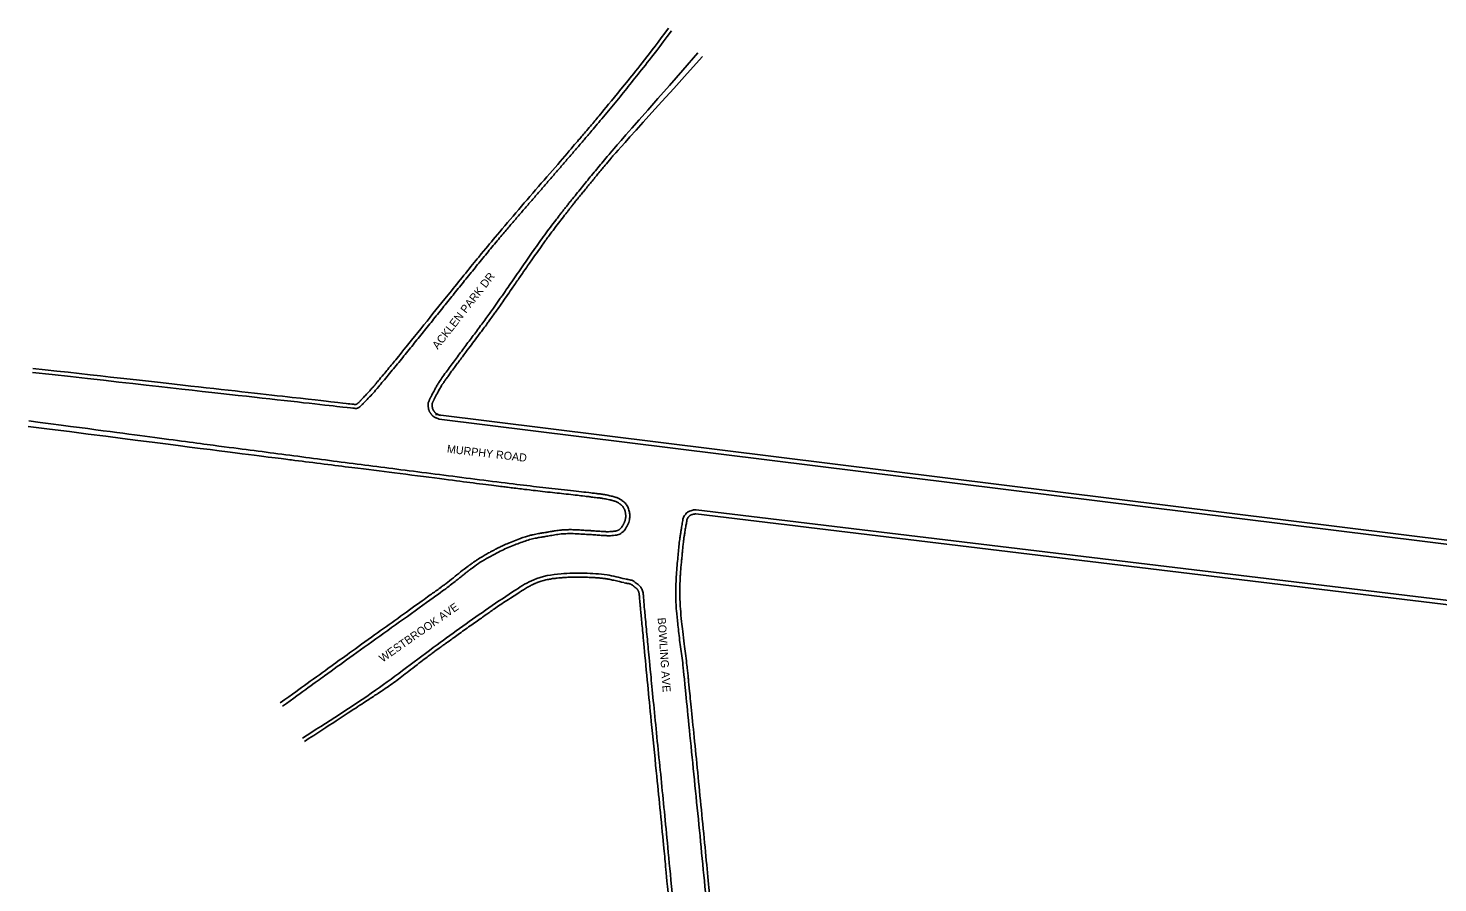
# Model space of a CAD drawing. Extents: x 1723992 to 1732080, y 650782 to 665122.
# Drawn here: x 1723992 to 1725049, y 658436 to 659077 of the extents above; entities that cross this region are included whole.
import ezdxf

# ---------------------------------------------------------------- set-up
doc = ezdxf.new("R2010")
doc.units = 0
for name, color, linetype in [('SURVEY - TRANSPORTATION - Features', 7, 'Continuous'), ('SURVEY - TRANSPORTATION - Roads', 7, 'Continuous'), ('SURVEY - TRANSPORTATION - Roads Text', 7, 'Continuous')]:
    doc.layers.add(name, color=color, linetype=linetype)

msp = doc.modelspace()

# ---------------------------------------------------------------- linework, layer by layer
at = {"layer": 'SURVEY - TRANSPORTATION - Features'}
for points in [[(1724297.3, 658787.4), (1725146.1, 658682), (1725172, 658680.1), (1725213.9, 658676.9), (1725217.3, 658676.6)], [(1724492.5, 658712.9), (1725143.7, 658634.3)]]:
    msp.add_lwpolyline(points, dxfattribs=at)
for points in [[(1724472, 659077.2), (1724456.9, 659056.9), (1724441.2, 659037.1), (1724420.9, 659012.6), (1724416.8, 659007.6), (1724408.4, 658997.7), (1724404.2, 658992.8), (1724391.6, 658978), (1724374.5, 658958.4), (1724357.6, 658938.8), (1724340.8, 658918.9), (1724332.5, 658908.9), (1724307.9, 658878.7), (1724291.7, 658858.4), (1724271.3, 658833.2), (1724265.2, 658825.7), (1724258, 658816.9), (1724254.3, 658812.6), (1724252.6, 658810.5), (1724252, 658809.8), (1724251.7, 658809.4), (1724251.6, 658809.3), (1724251.2, 658808.8), (1724251, 658808.5), (1724248.6, 658805.9), (1724246.5, 658803.5), (1724243.7, 658800.6), (1724242.8, 658799.7), (1724241.9, 658798.7), (1724241.4, 658798.2), (1724241.2, 658798), (1724241.2, 658797.9), (1724241, 658797.8), (1724240.9, 658797.7), (1724240.3, 658797), (1724239.8, 658796.5), (1724239.2, 658795.9), (1724238.9, 658795.7), (1724238.6, 658795.5), (1724238.5, 658795.4), (1724238.3, 658795.3), (1724238.3, 658795.3), (1724238.3, 658795.3), (1724238.3, 658795.3), (1724238.3, 658795.3), (1724238.2, 658795.2), (1724238.2, 658795.2), (1724238, 658795.1), (1724237.9, 658795.1), (1724237.6, 658795.1), (1724237.3, 658795), (1724237, 658795.1), (1724237, 658795.1), (1724236.9, 658795.1), (1724236.9, 658795.1), (1724236.8, 658795.1), (1724236.8, 658795.1), (1724236.7, 658795.1), (1724236.5, 658795.1), (1724235.8, 658795.2), (1724233.6, 658795.4), (1724228.4, 658796), (1724197.7, 658799.5), (1724119.6, 658808.2), (1724044.7, 658816.6), (1723995.6, 658822.1)], [(1724497.5, 659055.9), (1724432.4, 658983.8), (1724429.1, 658979.8), (1724424, 658973.7), (1724422.3, 658971.7), (1724418.9, 658967.6), (1724417.2, 658965.5), (1724413.8, 658961.4), (1724412.1, 658959.3), (1724408.8, 658955.2), (1724407.1, 658953.1), (1724403.7, 658949), (1724402.1, 658946.9), (1724399.6, 658943.8), (1724398.7, 658942.7), (1724397.1, 658940.6), (1724396.3, 658939.6), (1724392.1, 658934.3), (1724388.9, 658930.1), (1724384.1, 658923.7), (1724382.5, 658921.6), (1724379.4, 658917.3), (1724377.9, 658915.1), (1724373.2, 658908.6), (1724370.1, 658904.3), (1724364, 658895.5), (1724361, 658891.1), (1724354.9, 658882.3), (1724351.9, 658877.9), (1724347.3, 658871.3), (1724345.8, 658869.1), (1724342.7, 658864.7), (1724341.1, 658862.6), (1724337.9, 658858.2), (1724336.4, 658856), (1724333.2, 658851.7), (1724331.6, 658849.6), (1724326.8, 658843.1), (1724323.6, 658838.9), (1724318.8, 658832.4), (1724317.2, 658830.3), (1724314, 658826), (1724312.4, 658823.9), (1724309.2, 658819.6), (1724307.7, 658817.4), (1724305.4, 658814.2), (1724304.4, 658812.8), (1724303.5, 658811.5), (1724303.1, 658810.9), (1724302.9, 658810.7), (1724302.4, 658809.9), (1724302.1, 658809.4), (1724301.1, 658807.8), (1724300.4, 658806.6), (1724299.5, 658804.9), (1724299.2, 658804.3), (1724298.5, 658803.1), (1724297.9, 658802), (1724297.3, 658800.8), (1724296.9, 658800.1), (1724296.8, 658800), (1724296.7, 658799.7), (1724296.6, 658799.6), (1724296.4, 658799.1), (1724296.3, 658798.8), (1724296.1, 658798.4), (1724296, 658798.2), (1724295.9, 658798), (1724295.9, 658797.9), (1724295.8, 658797.8), (1724295.6, 658797.4), (1724295.5, 658797.1), (1724295.2, 658796.5), (1724295.1, 658796.3), (1724295, 658796), (1724295, 658795.9), (1724295, 658795.9), (1724295, 658795.9), (1724294.9, 658795.9), (1724294.9, 658795.8), (1724294.9, 658795.8), (1724294.9, 658795.7), (1724294.9, 658795.6), (1724294.8, 658795.4), (1724294.8, 658795.2), (1724294.8, 658794.8), (1724294.8, 658794.6), (1724294.8, 658794.3), (1724294.8, 658794.2), (1724294.8, 658794.1), (1724294.8, 658794.1), (1724294.8, 658794), (1724294.8, 658793.8), (1724294.9, 658793.6), (1724294.9, 658793.2), (1724295, 658793), (1724295.1, 658792.5), (1724295.1, 658792.2), (1724295.2, 658791.9), (1724295.2, 658791.8), (1724295.3, 658791.8), (1724295.3, 658791.7), (1724295.3, 658791.7), (1724295.3, 658791.7), (1724295.3, 658791.6), (1724295.4, 658791.5), (1724295.5, 658791.2), (1724295.6, 658791), (1724295.7, 658790.7), (1724295.8, 658790.6), (1724295.9, 658790.4), (1724296, 658790.3), (1724296.2, 658790.1), (1724296.2, 658790), (1724296.4, 658789.8), (1724296.5, 658789.6), (1724296.8, 658789.3), (1724296.9, 658789.1), (1724297.1, 658788.9), (1724297.1, 658788.9), (1724297.2, 658788.8), (1724297.2, 658788.8), (1724297.2, 658788.8), (1724297.2, 658788.8), (1724297.4, 658788.7), (1724297.5, 658788.6), (1724297.7, 658788.4), (1724297.9, 658788.2), (1724298.2, 658788), (1724298.4, 658788), (1724298.5, 658787.9), (1724298.5, 658787.9), (1724298.6, 658787.9), (1724298.6, 658787.9), (1724298.6, 658787.8), (1724298.7, 658787.8), (1724299, 658787.7), (1724299.8, 658787.4), (1724300.6, 658787), (1724301.2, 658786.8)], [(1723992, 658778.6), (1724166.8, 658756.2), (1724189.6, 658753.4), (1724238.4, 658747.3), (1724264.5, 658744), (1724303.6, 658739), (1724323.2, 658736.5), (1724342.8, 658734), (1724352.5, 658732.8), (1724355.8, 658732.4), (1724362.4, 658731.6), (1724365.6, 658731.2), (1724382, 658729.3), (1724395.1, 658727.9), (1724409.7, 658726.2), (1724411.4, 658726), (1724414.6, 658725.6), (1724416.2, 658725.4), (1724418.7, 658725.1), (1724419.9, 658725), (1724421.2, 658724.8), (1724421.7, 658724.7), (1724421.9, 658724.7), (1724422, 658724.7), (1724422.3, 658724.6), (1724424, 658724.4), (1724425.7, 658724), (1724428, 658723.5), (1724428.8, 658723.3), (1724430, 658723), (1724430.6, 658722.8), (1724431.2, 658722.7), (1724431.4, 658722.6), (1724431.5, 658722.6), (1724431.6, 658722.6), (1724431.7, 658722.5), (1724431.7, 658722.5), (1724432.4, 658722.3), (1724433, 658722), (1724434.2, 658721.4), (1724434.8, 658721), (1724435.5, 658720.5), (1724435.7, 658720.4), (1724435.9, 658720.2), (1724436, 658720.1), (1724436.1, 658720), (1724436.2, 658720), (1724436.5, 658719.7), (1724436.8, 658719.5), (1724437.4, 658718.9), (1724437.8, 658718.5), (1724438.3, 658717.7), (1724438.5, 658717.4), (1724438.8, 658716.8), (1724438.9, 658716.6), (1724439.3, 658715.7), (1724439.5, 658715.1), (1724439.7, 658714.1), (1724439.7, 658713.7), (1724439.8, 658713), (1724439.9, 658712.7), (1724440, 658711.6), (1724440, 658711), (1724439.9, 658710), (1724439.9, 658709.7), (1724439.8, 658709.1), (1724439.7, 658708.8), (1724439.5, 658707.9), (1724439.2, 658707.2), (1724438.8, 658706.3), (1724438.7, 658705.9), (1724438.4, 658705.4), (1724438.3, 658705.2), (1724438.1, 658704.9), (1724438, 658704.7), (1724437.6, 658703.9), (1724437.2, 658703.3), (1724436.5, 658702.4), (1724436.1, 658702), (1724435.4, 658701.4), (1724435.2, 658701.2), (1724434.7, 658700.9), (1724434.4, 658700.7), (1724433.6, 658700.4), (1724433.1, 658700.2), (1724432.3, 658700.1), (1724432.2, 658700), (1724432, 658700), (1724431.9, 658700), (1724431.8, 658700), (1724431.8, 658700), (1724431.8, 658700), (1724431.7, 658700), (1724431.6, 658700), (1724431.2, 658699.9), (1724430.7, 658699.9), (1724428.7, 658699.7), (1724427.2, 658699.6), (1724425.6, 658699.6), (1724425.3, 658699.6), (1724425, 658699.6), (1724424.9, 658699.7), (1724424.8, 658699.7), (1724424.7, 658699.7), (1724424.3, 658699.7), (1724423, 658699.8), (1724421.8, 658699.8), (1724419.3, 658700), (1724417.7, 658700.1), (1724415.2, 658700.3), (1724414.2, 658700.4), (1724413.1, 658700.4), (1724412.7, 658700.5), (1724412.5, 658700.5), (1724411.9, 658700.5), (1724411.5, 658700.5), (1724409.5, 658700.6), (1724407.8, 658700.8), (1724402.8, 658701), (1724399.5, 658701.2), (1724395.7, 658701.1), (1724395.2, 658701.1), (1724394.6, 658701.1), (1724394.4, 658701.1), (1724393.9, 658701.1), (1724392.8, 658701), (1724391.7, 658700.9), (1724389.2, 658700.6), (1724387.5, 658700.4), (1724384.2, 658699.8), (1724382.6, 658699.5), (1724379.3, 658699), (1724377.7, 658698.7), (1724374.4, 658698.1), (1724372.8, 658697.8), (1724370.3, 658697.3), (1724369.4, 658697.1), (1724367.8, 658696.7), (1724366.9, 658696.4), (1724362.8, 658695.2), (1724359.7, 658694), (1724353.5, 658691.6), (1724350.4, 658690.3), (1724345.8, 658688.2), (1724344.3, 658687.5), (1724342.4, 658686.5), (1724342, 658686.3), (1724341.3, 658685.9), (1724340.2, 658685.3), (1724339.1, 658684.7), (1724335.4, 658682.7), (1724332.5, 658681), (1724328.2, 658678.3), (1724326.8, 658677.4), (1724324.8, 658675.9), (1724324.1, 658675.4), (1724323, 658674.7), (1724322.7, 658674.4), (1724322, 658673.9), (1724321.7, 658673.7), (1724316, 658669.4), (1724311, 658665.2), (1724304.6, 658660.2), (1724303.3, 658659.3), (1724301.6, 658658.1), (1724301.3, 658657.8), (1724300.7, 658657.4), (1724299.7, 658656.6), (1724296, 658654), (1724287.3, 658647.8), (1724268.6, 658634.3), (1724252.6, 658622.8), (1724231.2, 658607.5), (1724220.6, 658599.8), (1724200.3, 658585.1), (1724190.6, 658578.2), (1724181, 658571.2)], [(1724525.8, 658181.9), (1724521.7, 658225.8), (1724515.5, 658292.4), (1724509.3, 658359), (1724506.1, 658393.1), (1724505.1, 658404.5), (1724502.9, 658427.2), (1724497.4, 658484), (1724491.8, 658540.7), (1724487.1, 658587.5), (1724487, 658588.9), (1724486.7, 658591.8), (1724486.2, 658596.1), (1724485.7, 658600.3), (1724484.7, 658608.9), (1724484, 658614.5), (1724482.6, 658625.8), (1724481.9, 658631.4), (1724480.9, 658642.7), (1724480.6, 658648.3), (1724480.5, 658656.7), (1724480.6, 658659.5), (1724480.8, 658665.1), (1724481, 658667.9), (1724481.3, 658672.2), (1724481.5, 658674.3), (1724481.7, 658676.4), (1724481.9, 658677.8), (1724481.9, 658678.5), (1724482.3, 658682.1), (1724482.5, 658684.9), (1724482.9, 658689.2), (1724483.1, 658690.5), (1724483.3, 658692.6), (1724483.4, 658693.5), (1724483.6, 658694.3), (1724483.6, 658694.7), (1724483.6, 658694.9), (1724483.7, 658695.4), (1724484.2, 658698.5), (1724484.8, 658702.4), (1724485.5, 658706.2), (1724485.7, 658707.5), (1724485.8, 658708.1), (1724485.8, 658708.3), (1724485.8, 658708.5), (1724485.8, 658708.5), (1724485.8, 658708.5), (1724485.8, 658708.5), (1724485.8, 658708.5), (1724485.9, 658708.9), (1724486.1, 658709.2), (1724486.5, 658710), (1724486.9, 658710.5), (1724487.3, 658711), (1724487.3, 658711), (1724487.4, 658711), (1724487.4, 658711.1), (1724487.5, 658711.2), (1724487.5, 658711.2), (1724487.6, 658711.3), (1724487.7, 658711.4), (1724487.9, 658711.6), (1724488.1, 658711.7), (1724488.4, 658711.9), (1724488.6, 658712), (1724488.8, 658712.1), (1724488.8, 658712.1), (1724488.9, 658712.2), (1724488.9, 658712.2), (1724489, 658712.2), (1724489.3, 658712.3), (1724489.5, 658712.4), (1724490.2, 658712.6), (1724490.7, 658712.8), (1724491.7, 658712.9), (1724492.1, 658712.9), (1724492.5, 658712.9)], [(1724199.2, 658542.4), (1724209, 658548.7), (1724223.6, 658558.3), (1724240.6, 658569.4), (1724249.2, 658575), (1724252.8, 658577.4), (1724254.4, 658578.4), (1724254.7, 658578.6), (1724255.3, 658579), (1724256.2, 658579.6), (1724257.1, 658580.2), (1724267.5, 658587.3), (1724276.7, 658594.5), (1724290.5, 658605.2), (1724295.1, 658608.7), (1724301, 658612.9), (1724302.2, 658613.8), (1724304.5, 658615.5), (1724308.1, 658618), (1724316.3, 658624), (1724325.8, 658630.7), (1724334.2, 658636.6), (1724337.7, 658639.1), (1724339.5, 658640.3), (1724340.1, 658640.8), (1724341.3, 658641.6), (1724341.9, 658642), (1724347.2, 658645.7), (1724352.1, 658648.8), (1724357.6, 658652.4), (1724358.2, 658652.8), (1724359.1, 658653.4), (1724359.4, 658653.6), (1724360, 658654), (1724361.5, 658655), (1724363, 658655.9), (1724366.6, 658658.1), (1724369.1, 658659.4), (1724371.8, 658660.7), (1724372, 658660.7), (1724372.3, 658660.9), (1724372.5, 658661), (1724373, 658661.2), (1724373.9, 658661.6), (1724374.9, 658661.9), (1724376.8, 658662.6), (1724378.1, 658663), (1724382.2, 658663.9), (1724384.9, 658664.4), (1724389.1, 658664.9), (1724390.5, 658665), (1724393.4, 658665.2), (1724397.7, 658665.5), (1724402, 658665.6), (1724405.5, 658665.6), (1724406.6, 658665.6), (1724407.7, 658665.5), (1724408.4, 658665.5), (1724408.7, 658665.5), (1724410.6, 658665.4), (1724412, 658665.4), (1724416.3, 658665.2), (1724419.1, 658665), (1724422.6, 658664.7), (1724423.7, 658664.5), (1724424.7, 658664.4), (1724425.4, 658664.3), (1724425.8, 658664.2), (1724427.5, 658663.9), (1724428.9, 658663.6), (1724433.1, 658662.8), (1724435.9, 658662.1), (1724438.6, 658661.4)], [(1724438.8, 658661.3), (1724440.2, 658661), (1724441.6, 658660.8), (1724443, 658660.5), (1724443.1, 658660.5), (1724443.1, 658660.5), (1724443.1, 658660.4), (1724443.2, 658660.4), (1724443.2, 658660.4), (1724443.3, 658660.4), (1724443.4, 658660.4), (1724443.7, 658660.3), (1724443.8, 658660.2), (1724444.4, 658659.9), (1724444.9, 658659.6), (1724445.6, 658659), (1724445.9, 658658.8), (1724446.3, 658658.5), (1724446.4, 658658.4), (1724446.7, 658658.1), (1724446.8, 658658), (1724447.5, 658657.5), (1724448, 658657.1), (1724448.5, 658656.6), (1724448.6, 658656.4), (1724448.8, 658656.2), (1724448.9, 658656.1), (1724448.9, 658656), (1724449, 658655.9), (1724449, 658655.9), (1724449, 658655.8), (1724449, 658655.8), (1724449.1, 658655.8), (1724449.4, 658655.2), (1724449.6, 658654.8), (1724449.9, 658653.8), (1724450, 658653.3), (1724450.1, 658652.8), (1724450.1, 658652.7), (1724450.1, 658652.6), (1724450.1, 658652.6), (1724450.1, 658652.6), (1724450.1, 658652.5), (1724450.1, 658652.3), (1724450.2, 658651.7), (1724450.3, 658649.9), (1724450.5, 658648.1), (1724450.7, 658646), (1724450.7, 658645.3), (1724450.9, 658643.9), (1724450.9, 658643.2), (1724451.1, 658641.2), (1724452.3, 658628.7), (1724453.5, 658616.3), (1724456.6, 658583), (1724458.8, 658560.9), (1724463.2, 658516.6), (1724465.5, 658494.5), (1724468.7, 658461.3), (1724469.7, 658450.2), (1724471.8, 658428.1), (1724480, 658341.6), (1724488.2, 658255), (1724495.4, 658179.6)]]:
    msp.add_open_spline(points, degree=3, dxfattribs=at)
at = {"layer": 'SURVEY - TRANSPORTATION - Roads'}
for points in [[(1724300.1, 658784), (1725145.8, 658679), (1725171.8, 658677.1), (1725213.7, 658673.9), (1725229.6, 658672.6), (1725231.6, 658672.4), (1725247.5, 658671), (1725249.5, 658670.8), (1725265.4, 658669.2), (1725267.4, 658669), (1725268.8, 658668.9)], [(1724492.9, 658715.9), (1725141.9, 658637.7)]]:
    msp.add_lwpolyline(points, dxfattribs=at)
for points in [[(1724474.3, 659075.3), (1724465, 659062.7), (1724455.4, 659050.3), (1724445.6, 659038.1), (1724435.8, 659025.8), (1724425.9, 659013.7), (1724415.8, 659001.8), (1724410.1, 658995.1), (1724404.5, 658988.5), (1724398.8, 658981.9), (1724393.1, 658975.3), (1724387.4, 658968.7), (1724381.7, 658962.1), (1724376, 658955.5), (1724370.3, 658948.9), (1724364.6, 658942.3), (1724358.9, 658935.7), (1724353.2, 658929.1), (1724347.6, 658922.4), (1724339.7, 658913), (1724331.8, 658903.5), (1724324.1, 658893.9), (1724316.3, 658884.3), (1724308.6, 658874.7), (1724300.8, 658865), (1724293.1, 658855.4), (1724285.4, 658845.8), (1724277.6, 658836.2), (1724269.9, 658826.6), (1724262, 658817.1), (1724254.1, 658807.6), (1724250.7, 658803.5), (1724246.9, 658799.7), (1724243.3, 658795.8), (1724242.2, 658794.7), (1724241.3, 658793.6), (1724239.9, 658792.7), (1724238.8, 658792.1), (1724237.6, 658792), (1724236.5, 658792.1), (1724156.1, 658801.1), (1724075.7, 658810.1), (1723995.3, 658819.1)], [(1724494.1, 659058.7), (1724429.6, 658985.1), (1724425.8, 658980.6), (1724422.1, 658976.1), (1724418.2, 658971.4), (1724414.3, 658966.8), (1724410.5, 658962.1), (1724406.7, 658957.4), (1724402.9, 658952.7), (1724399.1, 658948), (1724397.2, 658945.6), (1724395.3, 658943.2), (1724393.4, 658940.9), (1724391.6, 658938.5), (1724389.7, 658936.1), (1724387.9, 658933.7), (1724383.5, 658928), (1724379.2, 658922.3), (1724375.1, 658916.4), (1724370.9, 658910.6), (1724366.8, 658904.8), (1724362.8, 658898.9), (1724358.7, 658893), (1724354.6, 658887.1), (1724350.6, 658881.2), (1724348.5, 658878.3), (1724346.5, 658875.4), (1724344.4, 658872.4), (1724342.4, 658869.5), (1724340.3, 658866.6), (1724338.2, 658863.7), (1724335.1, 658859.4), (1724332, 658855.2), (1724328.9, 658850.9), (1724325.7, 658846.7), (1724322.5, 658842.5), (1724319.4, 658838.3), (1724316.2, 658834), (1724313.1, 658829.8), (1724310, 658825.6), (1724306.8, 658821.3), (1724303.7, 658817.1), (1724300.7, 658812.7), (1724299.1, 658810.4), (1724297.8, 658808), (1724296.4, 658805.5), (1724295.6, 658804.1), (1724294.9, 658802.7), (1724294.2, 658801.3), (1724293.8, 658800.6), (1724293.5, 658799.9), (1724293.1, 658799.2), (1724292.8, 658798.5), (1724292.5, 658797.7), (1724292.2, 658797), (1724291.9, 658796.3), (1724291.8, 658795.6), (1724291.8, 658794.9), (1724291.8, 658794.6), (1724291.8, 658794.2), (1724291.8, 658793.8), (1724291.9, 658793.5), (1724291.9, 658793.1), (1724292, 658792.8), (1724292.1, 658792.1), (1724292.2, 658791.4), (1724292.4, 658790.8), (1724292.6, 658790.1), (1724293, 658789.5), (1724293.3, 658788.9), (1724293.6, 658788.5), (1724293.9, 658788.1), (1724294.2, 658787.7), (1724294.5, 658787.3), (1724294.8, 658786.9), (1724295.2, 658786.6), (1724295.8, 658786), (1724296.6, 658785.4), (1724297.4, 658785.1), (1724298.3, 658784.7), (1724299.2, 658784.4), (1724300.1, 658784)], [(1723992.4, 658782.7), (1724039.8, 658776.5), (1724087.3, 658770.2), (1724134.7, 658763.9), (1724158.5, 658760.8), (1724182.2, 658757.7), (1724206, 658754.6), (1724229.7, 658751.4), (1724253.4, 658748.4), (1724277.2, 658745.4), (1724303.7, 658742), (1724330.3, 658738.6), (1724356.8, 658735.3), (1724375.4, 658733), (1724394, 658731.1), (1724412.5, 658728.9), (1724415.8, 658728.5), (1724419.1, 658728.1), (1724422.3, 658727.7), (1724425.7, 658727.2), (1724429, 658726.4), (1724432.3, 658725.5), (1724434.3, 658724.9), (1724436.1, 658723.8), (1724437.8, 658722.5), (1724439.2, 658721.5), (1724440.2, 658720.4), (1724441.1, 658718.9), (1724441.9, 658717.4), (1724442.4, 658715.9), (1724442.7, 658714.3), (1724443, 658712.7), (1724443.1, 658711.1), (1724442.9, 658709.5), (1724442.6, 658707.5), (1724441.9, 658705.6), (1724440.9, 658703.6), (1724439.9, 658701.8), (1724438.9, 658700.2), (1724437.1, 658698.9), (1724435.5, 658697.8), (1724433.9, 658697.2), (1724432.1, 658697), (1724429.7, 658696.7), (1724427.2, 658696.5), (1724424.8, 658696.7), (1724420.6, 658696.9), (1724416.4, 658697.3), (1724412.2, 658697.5), (1724406.4, 658697.8), (1724400.6, 658698.3), (1724394.9, 658698.1), (1724390.3, 658697.9), (1724385.8, 658697), (1724381.3, 658696.3), (1724377.9, 658695.7), (1724374.6, 658695.2), (1724371.4, 658694.5), (1724366.8, 658693.4), (1724362.4, 658691.9), (1724358, 658690.2), (1724353.1, 658688.3), (1724348.2, 658686.2), (1724343.5, 658683.7), (1724337.1, 658680.3), (1724330.9, 658676.8), (1724325.1, 658672.5), (1724323.2, 658671.1), (1724321.3, 658669.7), (1724319.5, 658668.2), (1724317.6, 658666.7), (1724315.8, 658665.3), (1724314, 658663.8), (1724310.3, 658660.9), (1724306.6, 658658), (1724302.8, 658655.2), (1724279.3, 658638.2), (1724255.6, 658621.4), (1724232, 658604.4), (1724215.5, 658592.5), (1724199.1, 658580.6), (1724182.6, 658568.7)], [(1724522.9, 658181.7), (1724516.5, 658250.2), (1724510.1, 658318.7), (1724503.7, 658387.2), (1724497.4, 658454.6), (1724490.6, 658522), (1724483.9, 658589.4), (1724482.6, 658603.1), (1724480.5, 658616.6), (1724479.1, 658630.2), (1724478, 658639.8), (1724477.3, 658649.4), (1724477.6, 658659), (1724477.8, 658665.8), (1724478.3, 658672.5), (1724479, 658679.3), (1724479.5, 658684.7), (1724479.9, 658690.1), (1724480.7, 658695.4), (1724481.1, 658698), (1724481.5, 658700.6), (1724481.9, 658703.1), (1724482.2, 658705.1), (1724482.5, 658707), (1724482.9, 658709), (1724483.1, 658710.4), (1724484, 658711.7), (1724485, 658712.9), (1724485.8, 658713.9), (1724486.7, 658714.5), (1724487.8, 658715), (1724489.5, 658715.6), (1724491.2, 658716.1), (1724492.9, 658715.9)], [(1724439.4, 658664.2), (1724440.8, 658664), (1724442.3, 658663.7), (1724443.7, 658663.4), (1724445.6, 658663), (1724447.1, 658661.6), (1724448.6, 658660.4), (1724449.8, 658659.5), (1724450.8, 658658.7), (1724451.6, 658657.4), (1724452.4, 658656), (1724452.9, 658654.5), (1724453.1, 658652.9), (1724453.4, 658649.7), (1724453.6, 658646.4), (1724453.9, 658643.2), (1724455.3, 658628.3), (1724456.7, 658613.3), (1724458.2, 658598.3), (1724463, 658548.7), (1724468.1, 658499.1), (1724472.8, 658449.4), (1724481.3, 658359.6), (1724489.8, 658269.7), (1724498.3, 658179.8)]]:
    msp.add_open_spline(points, degree=3, dxfattribs=at)
msp.add_spline([(1724197.6, 658544.9), (1724252.5, 658580.8), (1724298.5, 658614.8), (1724337.4, 658642.5), (1724357.7, 658656.1), (1724371, 658663.6), (1724391.5, 658668.1), (1724409, 658668.5), (1724426, 658667.2), (1724439.4, 658664.2)], degree=3, dxfattribs=at)

# ---------------------------------------------------------------- texts
at = {"layer": 'SURVEY - TRANSPORTATION - Roads Text'}
for s, rotation, p in [('ACKLEN PARK DR', 51.9926, (1724299.1, 658835.9)), ('MURPHY ROAD ', 353.3738, (1724305.7, 658758.9)), ('WESTBROOK AVE', 35.0347, (1724257.7, 658601.4)), ('BOWLING AVE', 273.964, (1724463.9, 658635))]:
    msp.add_text(s, height=6, rotation=rotation, dxfattribs=at).set_placement(p)

doc.saveas('drawing.dxf')
